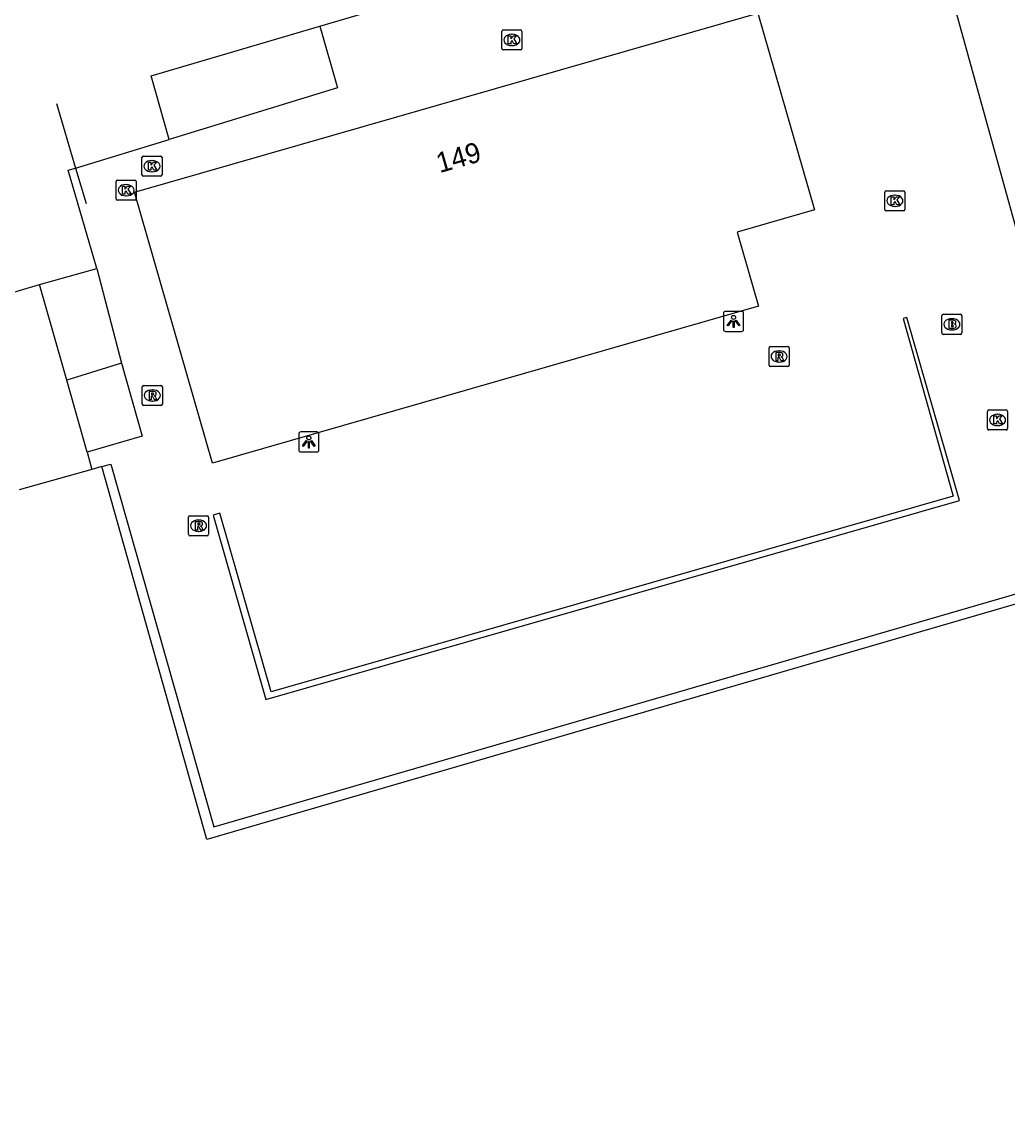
# Model space of a CAD drawing. Extents: x 162417 to 163721, y 384268 to 385416.
# Drawn here: x 162874.2 to 162923.2, y 384503.5 to 384558.2 of the extents above; entities that cross this region are included whole.
import ezdxf

# ---------------------------------------------------------------- set-up
doc = ezdxf.new("R2010")
doc.units = 0
for name, color, linetype in [('IMGEO_Brandkraan', 7, 'Continuous'), ('IMGEO_Hek', 7, 'Continuous'), ('IMGEO_Kolk', 7, 'Continuous'), ('IMGEO_Lichtpunt', 7, 'Continuous'), ('IMGEO_Muur', 7, 'Continuous'), ('IMGEO_Pand', 7, 'Continuous'), ('IMGEO_Pand_nummerreeks', 7, 'Continuous'), ('IMGEO_Rijbaan_lokaal_gesloten', 7, 'Continuous'), ('IMGEO_Rioolput', 7, 'Continuous'), ('IMGEO_Voetpad_open', 7, 'Continuous')]:
    doc.layers.add(name, color=color, linetype=linetype)

msp = doc.modelspace()

# ---------------------------------------------------------------- linework, layer by layer
at = {"layer": 'IMGEO_Brandkraan'}
for p, q in [((162919.957, 384542.765), (162919.957, 384543.617)), ((162920.032, 384543.691), (162920.884, 384543.691)), ((162920.958, 384543.617), (162920.958, 384542.765)), ((162920.445, 384543.471), (162920.47, 384543.471)), ((162920.884, 384542.691), (162920.032, 384542.691)), ((162920.468, 384542.911), (162920.443, 384542.911))]:
    msp.add_line(p, q, dxfattribs=at)
for points in [[(162919.957, 384542.765), (162919.957, 384543.617)], [(162920.032, 384543.691), (162920.884, 384543.691)], [(162920.958, 384543.617), (162920.958, 384542.765)], [(162920.305, 384543.391), (162920.305, 384542.991), (162920.518, 384542.991)], [(162920.536, 384543.391), (162920.305, 384543.391)], [(162920.484, 384543.31), (162920.43, 384543.31), (162920.43, 384543.234)], [(162920.43, 384543.234), (162920.483, 384543.234)], [(162920.492, 384543.158), (162920.43, 384543.158), (162920.43, 384543.077)], [(162920.43, 384543.077), (162920.492, 384543.077)], [(162920.884, 384542.691), (162920.032, 384542.691)]]:
    msp.add_lwpolyline(points, dxfattribs=at)
for centre, radius, start, end in [((162920.034, 384543.615), 0.0765, 91.552, 178.448), ((162920.034, 384543.615), 0.0765, 91.552, 178.448), ((162920.882, 384543.615), 0.0765, 1.552, 88.448), ((162920.882, 384543.615), 0.0765, 1.552, 88.448), ((162920.485, 384543.272), 0.0379, 267.8285, 90.9355), ((162920.493, 384543.117), 0.0404, 269.8759, 90.5077), ((162920.524, 384543.242), 0.251, 268.6676, 293.5347), ((162920.54, 384543.246), 0.145, 59.4692, 91.5367), ((162920.565, 384543.293), 0.0922, 285.5137, 58.1501), ((162920.57, 384543.101), 0.105, 301.3115, 78.989), ((162920.034, 384542.767), 0.0765, 181.552, 268.448), ((162920.034, 384542.767), 0.0765, 181.552, 268.448), ((162920.882, 384542.767), 0.0765, 271.552, 358.448), ((162920.882, 384542.767), 0.0765, 271.552, 358.448)]:
    msp.add_arc(centre, radius, start, end, dxfattribs=at)
for centre, major_axis, ratio, start_param, end_param in [((162920.444, 384543.191), (-0.387, 0.002), 0.722429, 4.712389, 7.853982), ((162920.469, 384543.191), (-0.39, 0.002), 0.717154, 1.570796, 4.712389)]:
    msp.add_ellipse(centre, major_axis=major_axis, ratio=ratio, start_param=start_param, end_param=end_param, dxfattribs=at)
at = {"layer": 'IMGEO_Hek'}
for points in [[(162875.908, 384554.172), (162876.859, 384550.963)], [(162876.859, 384550.963), (162877.381, 384549.2)]]:
    msp.add_lwpolyline(points, dxfattribs=at)
at = {"layer": 'IMGEO_Kolk'}
for p, q in [((162898.14, 384557.832), (162898.992, 384557.832)), ((162898.065, 384556.906), (162898.065, 384557.758)), ((162898.553, 384557.612), (162898.578, 384557.612)), ((162899.066, 384557.758), (162899.066, 384556.906)), ((162898.992, 384556.832), (162898.14, 384556.832)), ((162898.576, 384557.052), (162898.551, 384557.052)), ((162880.159, 384550.626), (162880.159, 384551.478)), ((162880.234, 384551.552), (162881.086, 384551.552)), ((162880.647, 384551.332), (162880.672, 384551.332)), ((162881.16, 384551.478), (162881.16, 384550.626)), ((162880.67, 384550.772), (162880.645, 384550.772)), ((162878.873, 384549.433), (162878.873, 384550.285)), ((162878.948, 384550.359), (162879.8, 384550.359)), ((162879.361, 384550.139), (162879.386, 384550.139)), ((162879.874, 384550.285), (162879.874, 384549.433)), ((162881.086, 384550.552), (162880.234, 384550.552)), ((162917.121, 384548.907), (162917.121, 384549.759)), ((162917.196, 384549.833), (162918.048, 384549.833)), ((162917.609, 384549.613), (162917.634, 384549.613)), ((162918.122, 384549.759), (162918.122, 384548.907)), ((162879.8, 384549.359), (162878.948, 384549.359)), ((162879.384, 384549.579), (162879.359, 384549.579)), ((162917.632, 384549.053), (162917.607, 384549.053)), ((162918.048, 384548.833), (162917.196, 384548.833)), ((162922.227, 384538.009), (162922.227, 384538.861)), ((162922.302, 384538.935), (162923.154, 384538.935)), ((162922.715, 384538.715), (162922.74, 384538.715)), ((162923.228, 384538.861), (162923.228, 384538.009)), ((162922.738, 384538.155), (162922.713, 384538.155)), ((162923.154, 384537.935), (162922.302, 384537.935))]:
    msp.add_line(p, q, dxfattribs=at)
for points in [[(162898.14, 384557.832), (162898.992, 384557.832)], [(162898.065, 384556.906), (162898.065, 384557.758)], [(162898.386, 384557.532), (162898.509, 384557.532), (162898.509, 384557.381), (162898.639, 384557.532), (162898.803, 384557.532), (162898.657, 384557.381), (162898.81, 384557.132), (162898.658, 384557.132), (162898.573, 384557.296), (162898.509, 384557.229), (162898.509, 384557.132), (162898.386, 384557.132), (162898.386, 384557.532)], [(162899.066, 384557.758), (162899.066, 384556.906)], [(162898.992, 384556.832), (162898.14, 384556.832)], [(162880.159, 384550.626), (162880.159, 384551.478)], [(162880.234, 384551.552), (162881.086, 384551.552)], [(162880.48, 384551.252), (162880.603, 384551.252), (162880.603, 384551.101), (162880.733, 384551.252), (162880.897, 384551.252), (162880.751, 384551.101), (162880.904, 384550.852), (162880.752, 384550.852), (162880.667, 384551.016), (162880.603, 384550.949), (162880.603, 384550.852), (162880.48, 384550.852), (162880.48, 384551.252)], [(162881.16, 384551.478), (162881.16, 384550.626)], [(162878.873, 384549.433), (162878.873, 384550.285)], [(162878.948, 384550.359), (162879.8, 384550.359)], [(162879.874, 384550.285), (162879.874, 384549.433)], [(162881.086, 384550.552), (162880.234, 384550.552)], [(162879.194, 384550.059), (162879.317, 384550.059), (162879.317, 384549.908), (162879.447, 384550.059), (162879.611, 384550.059), (162879.465, 384549.908), (162879.618, 384549.659), (162879.466, 384549.659), (162879.381, 384549.823), (162879.317, 384549.756), (162879.317, 384549.659), (162879.194, 384549.659), (162879.194, 384550.059)], [(162917.121, 384548.907), (162917.121, 384549.759)], [(162917.196, 384549.833), (162918.048, 384549.833)], [(162918.122, 384549.759), (162918.122, 384548.907)], [(162879.8, 384549.359), (162878.948, 384549.359)], [(162917.442, 384549.533), (162917.565, 384549.533), (162917.565, 384549.382), (162917.695, 384549.533), (162917.859, 384549.533), (162917.713, 384549.382), (162917.866, 384549.133), (162917.714, 384549.133), (162917.629, 384549.297), (162917.565, 384549.23), (162917.565, 384549.133), (162917.442, 384549.133), (162917.442, 384549.533)], [(162918.048, 384548.833), (162917.196, 384548.833)], [(162922.227, 384538.009), (162922.227, 384538.861)], [(162922.302, 384538.935), (162923.154, 384538.935)], [(162922.548, 384538.635), (162922.671, 384538.635), (162922.671, 384538.484), (162922.801, 384538.635), (162922.965, 384538.635), (162922.819, 384538.484), (162922.972, 384538.235), (162922.82, 384538.235), (162922.735, 384538.399), (162922.671, 384538.332), (162922.671, 384538.235), (162922.548, 384538.235), (162922.548, 384538.635)], [(162923.228, 384538.861), (162923.228, 384538.009)], [(162923.154, 384537.935), (162922.302, 384537.935)]]:
    msp.add_lwpolyline(points, dxfattribs=at)
for centre, start, end in [((162898.142, 384557.756), 91.552, 178.448), ((162898.142, 384557.756), 91.552, 178.448), ((162898.99, 384557.756), 1.552, 88.448), ((162898.99, 384557.756), 1.552, 88.448), ((162898.142, 384556.908), 181.552, 268.448), ((162898.142, 384556.908), 181.552, 268.448), ((162898.99, 384556.908), 271.552, 358.448), ((162898.99, 384556.908), 271.552, 358.448), ((162880.236, 384551.476), 91.552, 178.448), ((162880.236, 384551.476), 91.552, 178.448), ((162881.084, 384551.476), 1.552, 88.448), ((162881.084, 384551.476), 1.552, 88.448), ((162878.95, 384550.283), 91.552, 178.448), ((162878.95, 384550.283), 91.552, 178.448), ((162879.798, 384550.283), 1.552, 88.448), ((162879.798, 384550.283), 1.552, 88.448), ((162880.236, 384550.628), 181.552, 268.448), ((162880.236, 384550.628), 181.552, 268.448), ((162881.084, 384550.628), 271.552, 358.448), ((162881.084, 384550.628), 271.552, 358.448), ((162917.198, 384549.757), 91.552, 178.448), ((162917.198, 384549.757), 91.552, 178.448), ((162918.046, 384549.757), 1.552, 88.448), ((162918.046, 384549.757), 1.552, 88.448), ((162878.95, 384549.435), 181.552, 268.448), ((162878.95, 384549.435), 181.552, 268.448), ((162879.798, 384549.435), 271.552, 358.448), ((162879.798, 384549.435), 271.552, 358.448), ((162917.198, 384548.909), 181.552, 268.448), ((162917.198, 384548.909), 181.552, 268.448), ((162918.046, 384548.909), 271.552, 358.448), ((162918.046, 384548.909), 271.552, 358.448), ((162922.304, 384538.859), 91.552, 178.448), ((162922.304, 384538.859), 91.552, 178.448), ((162923.152, 384538.859), 1.552, 88.448), ((162923.152, 384538.859), 1.552, 88.448), ((162922.304, 384538.011), 181.552, 268.448), ((162922.304, 384538.011), 181.552, 268.448), ((162923.152, 384538.011), 271.552, 358.448), ((162923.152, 384538.011), 271.552, 358.448)]:
    msp.add_arc(centre, 0.0765, start, end, dxfattribs=at)
for centre, major_axis, ratio, start_param, end_param in [((162898.552, 384557.332), (-0.387, 0.002), 0.722429, 4.712389, 7.853982), ((162898.577, 384557.332), (-0.39, 0.002), 0.717154, 1.570796, 4.712389), ((162880.646, 384551.052), (-0.387, 0.002), 0.722429, 4.712389, 7.853982), ((162880.671, 384551.052), (-0.39, 0.002), 0.717154, 1.570796, 4.712389), ((162879.36, 384549.859), (-0.387, 0.002), 0.722429, 4.712389, 7.853982), ((162879.385, 384549.859), (-0.39, 0.002), 0.717154, 1.570796, 4.712389), ((162917.608, 384549.333), (-0.387, 0.002), 0.722429, 4.712389, 7.853982), ((162917.633, 384549.333), (-0.39, 0.002), 0.717154, 1.570796, 4.712389), ((162922.714, 384538.435), (-0.387, 0.002), 0.722429, 4.712389, 7.853982), ((162922.739, 384538.435), (-0.39, 0.002), 0.717154, 1.570796, 4.712389)]:
    msp.add_ellipse(centre, major_axis=major_axis, ratio=ratio, start_param=start_param, end_param=end_param, dxfattribs=at)
at = {"layer": 'IMGEO_Lichtpunt'}
for p, q in [((162909.095, 384543.737), (162909.095, 384542.93)), ((162909.095, 384543.737), (162909.095, 384542.93)), ((162909.997, 384543.832), (162909.189, 384543.832)), ((162909.997, 384543.832), (162909.189, 384543.832)), ((162910.091, 384542.93), (162910.091, 384543.737)), ((162910.091, 384542.93), (162910.091, 384543.737)), ((162909.189, 384542.836), (162909.997, 384542.836)), ((162909.189, 384542.836), (162909.997, 384542.836)), ((162887.964, 384537.744), (162887.964, 384536.937)), ((162887.964, 384537.744), (162887.964, 384536.937)), ((162888.866, 384537.839), (162888.058, 384537.839)), ((162888.866, 384537.839), (162888.058, 384537.839)), ((162888.96, 384536.937), (162888.96, 384537.744)), ((162888.96, 384536.937), (162888.96, 384537.744)), ((162888.058, 384536.843), (162888.866, 384536.843)), ((162888.058, 384536.843), (162888.866, 384536.843))]:
    msp.add_line(p, q, dxfattribs=at)
for points in [[(162909.469, 384543.401), (162909.508, 384543.373), (162909.32, 384543.111), (162909.282, 384543.138), (162909.469, 384543.401)], [(162909.571, 384543.353), (162909.618, 384543.353), (162909.618, 384543.031), (162909.571, 384543.031), (162909.571, 384543.353)], [(162909.681, 384543.373), (162909.719, 384543.4), (162909.906, 384543.138), (162909.867, 384543.11), (162909.681, 384543.373)], [(162888.338, 384537.408), (162888.377, 384537.38), (162888.189, 384537.118), (162888.151, 384537.145), (162888.338, 384537.408)], [(162888.44, 384537.36), (162888.487, 384537.36), (162888.487, 384537.038), (162888.44, 384537.038), (162888.44, 384537.36)], [(162888.55, 384537.38), (162888.588, 384537.407), (162888.775, 384537.145), (162888.736, 384537.117), (162888.55, 384537.38)]]:
    msp.add_lwpolyline(points, dxfattribs=at)
for centre in [(162909.594, 384543.535), (162888.463, 384537.542)]:
    msp.add_circle(centre, 0.0994, dxfattribs=at)
for centre, start, end in [((162909.189, 384543.737), 90, 180), ((162909.189, 384543.737), 90, 180), ((162909.997, 384543.737), 0, 90), ((162909.997, 384543.737), 0, 90), ((162909.189, 384542.93), 180, 270), ((162909.189, 384542.93), 180, 270), ((162909.997, 384542.93), 270, 0), ((162909.997, 384542.93), 270, 360), ((162888.058, 384537.744), 90, 180), ((162888.058, 384537.744), 90, 180), ((162888.866, 384537.744), 0, 90), ((162888.866, 384537.744), 0, 90), ((162888.058, 384536.937), 180, 270), ((162888.058, 384536.937), 180, 270), ((162888.866, 384536.937), 270, 0), ((162888.866, 384536.937), 270, 360)]:
    msp.add_arc(centre, 0.0946, start, end, dxfattribs=at)
at = {"layer": 'IMGEO_Muur'}
for points in [[(162918.22, 384543.528), (162918.03, 384543.473), (162920.528, 384534.642), (162892.486, 384526.608), (162886.585, 384524.917), (162884.04, 384533.796), (162883.705, 384533.701), (162886.331, 384524.539), (162920.833, 384534.428), (162918.22, 384543.528)], [(162878.17, 384536.114), (162878.614, 384536.239), (162883.731, 384518.208), (162927.298, 384530.854), (162927.217, 384531.137), (162927.658, 384531.274)], [(162968.826, 384503.475), (162935.509, 384505.709), (162935.475, 384505.306), (162933.994, 384505.388), (162934.026, 384506.507), (162934.243, 384506.512), (162927.431, 384530.386), (162883.395, 384517.577), (162878.17, 384536.114)]]:
    msp.add_lwpolyline(points, dxfattribs=at)
at = {"layer": 'IMGEO_Pand'}
msp.add_lwpolyline([(162910.835, 384544.088), (162883.663, 384536.285), (162879.794, 384549.759), (162910.81, 384558.667), (162913.62, 384548.884), (162909.775, 384547.78), (162910.835, 384544.088)], dxfattribs=at)
at = {"layer": 'IMGEO_Rijbaan_lokaal_gesloten'}
msp.add_lwpolyline([(162930.167, 384545.925), (162924.649, 384544.377), (162919.95, 384561.313)], dxfattribs=at)
at = {"layer": 'IMGEO_Rioolput'}
for p, q in [((162911.358, 384541.165), (162911.358, 384542.017)), ((162911.433, 384542.091), (162912.285, 384542.091)), ((162912.359, 384542.017), (162912.359, 384541.165)), ((162911.846, 384541.871), (162911.871, 384541.871)), ((162912.285, 384541.091), (162911.433, 384541.091)), ((162911.869, 384541.311), (162911.844, 384541.311)), ((162880.175, 384539.226), (162880.175, 384540.078)), ((162880.25, 384540.152), (162881.102, 384540.152)), ((162880.663, 384539.932), (162880.688, 384539.932)), ((162881.176, 384540.078), (162881.176, 384539.226)), ((162880.686, 384539.372), (162880.661, 384539.372)), ((162881.102, 384539.152), (162880.25, 384539.152)), ((162882.478, 384532.748), (162882.478, 384533.6)), ((162882.553, 384533.674), (162883.405, 384533.674)), ((162882.966, 384533.454), (162882.991, 384533.454)), ((162883.479, 384533.6), (162883.479, 384532.748)), ((162883.405, 384532.674), (162882.553, 384532.674)), ((162882.989, 384532.894), (162882.964, 384532.894))]:
    msp.add_line(p, q, dxfattribs=at)
for points in [[(162911.358, 384541.165), (162911.358, 384542.017)], [(162911.433, 384542.091), (162912.285, 384542.091)], [(162912.359, 384542.017), (162912.359, 384541.165)], [(162911.947, 384541.789), (162911.695, 384541.791), (162911.695, 384541.391)], [(162911.695, 384541.391), (162911.819, 384541.391), (162911.819, 384541.553), (162911.83, 384541.553)], [(162911.873, 384541.71), (162911.819, 384541.71), (162911.819, 384541.629)], [(162911.819, 384541.629), (162911.871, 384541.629)], [(162911.877, 384541.524), (162911.948, 384541.391), (162912.088, 384541.391), (162912.023, 384541.517)], [(162912.285, 384541.091), (162911.433, 384541.091)], [(162880.175, 384539.226), (162880.175, 384540.078)], [(162880.25, 384540.152), (162881.102, 384540.152)], [(162880.764, 384539.85), (162880.512, 384539.852), (162880.512, 384539.452)], [(162880.69, 384539.771), (162880.636, 384539.771), (162880.636, 384539.69)], [(162881.176, 384540.078), (162881.176, 384539.226)], [(162880.512, 384539.452), (162880.636, 384539.452), (162880.636, 384539.614), (162880.647, 384539.614)], [(162880.636, 384539.69), (162880.688, 384539.69)], [(162880.694, 384539.585), (162880.765, 384539.452), (162880.905, 384539.452), (162880.84, 384539.578)], [(162881.102, 384539.152), (162880.25, 384539.152)], [(162882.478, 384532.748), (162882.478, 384533.6)], [(162882.553, 384533.674), (162883.405, 384533.674)], [(162883.067, 384533.372), (162882.815, 384533.374), (162882.815, 384532.974)], [(162882.993, 384533.293), (162882.939, 384533.293), (162882.939, 384533.212)], [(162882.939, 384533.212), (162882.991, 384533.212)], [(162883.479, 384533.6), (162883.479, 384532.748)], [(162883.405, 384532.674), (162882.553, 384532.674)], [(162882.815, 384532.974), (162882.939, 384532.974), (162882.939, 384533.136), (162882.95, 384533.136)], [(162882.997, 384533.107), (162883.068, 384532.974), (162883.208, 384532.974), (162883.143, 384533.1)]]:
    msp.add_lwpolyline(points, dxfattribs=at)
for centre, radius, start, end in [((162911.435, 384542.015), 0.0765, 91.552, 178.448), ((162911.435, 384542.015), 0.0765, 91.552, 178.448), ((162912.283, 384542.015), 0.0765, 1.552, 88.448), ((162912.283, 384542.015), 0.0765, 1.552, 88.448), ((162911.829, 384541.5), 0.0533, 26.0293, 88.6989), ((162911.855, 384541.818), 0.19, 274.7715, 282.9687), ((162911.879, 384541.614), 0.0964, 77.0061, 93.1865), ((162911.893, 384541.671), 0.0378, 276.6634, 79.6772), ((162911.946, 384541.679), 0.109, 350.3612, 89.416), ((162911.944, 384541.679), 0.112, 277.5842, 350.9817), ((162911.928, 384541.464), 0.108, 29.5134, 73.7905), ((162911.435, 384541.167), 0.0765, 181.552, 268.448), ((162911.435, 384541.167), 0.0765, 181.552, 268.448), ((162912.283, 384541.167), 0.0765, 271.552, 358.448), ((162912.283, 384541.167), 0.0765, 271.552, 358.448), ((162880.252, 384540.076), 0.0765, 91.552, 178.448), ((162880.252, 384540.076), 0.0765, 91.552, 178.448), ((162880.696, 384539.675), 0.0964, 77.0061, 93.1865), ((162880.71, 384539.732), 0.0378, 276.6634, 79.6772), ((162880.763, 384539.74), 0.109, 350.3612, 89.416), ((162881.1, 384540.076), 0.0765, 1.552, 88.448), ((162881.1, 384540.076), 0.0765, 1.552, 88.448), ((162880.252, 384539.228), 0.0765, 181.552, 268.448), ((162880.252, 384539.228), 0.0765, 181.552, 268.448), ((162880.646, 384539.561), 0.0533, 26.0293, 88.6989), ((162880.672, 384539.879), 0.19, 274.7715, 282.9687), ((162880.761, 384539.74), 0.112, 277.5842, 350.9817), ((162880.745, 384539.525), 0.108, 29.5134, 73.7905), ((162881.1, 384539.228), 0.0765, 271.552, 358.448), ((162881.1, 384539.228), 0.0765, 271.552, 358.448), ((162882.555, 384533.598), 0.0765, 91.552, 178.448), ((162882.555, 384533.598), 0.0765, 91.552, 178.448), ((162882.975, 384533.401), 0.19, 274.7715, 282.9687), ((162882.999, 384533.197), 0.0964, 77.0061, 93.1865), ((162883.013, 384533.254), 0.0378, 276.6634, 79.6772), ((162883.066, 384533.262), 0.109, 350.3612, 89.416), ((162883.064, 384533.262), 0.112, 277.5842, 350.9817), ((162883.403, 384533.598), 0.0765, 1.552, 88.448), ((162883.403, 384533.598), 0.0765, 1.552, 88.448), ((162882.555, 384532.75), 0.0765, 181.552, 268.448), ((162882.555, 384532.75), 0.0765, 181.552, 268.448), ((162882.949, 384533.083), 0.0533, 26.0293, 88.6989), ((162883.048, 384533.047), 0.108, 29.5134, 73.7905), ((162883.403, 384532.75), 0.0765, 271.552, 358.448), ((162883.403, 384532.75), 0.0765, 271.552, 358.448)]:
    msp.add_arc(centre, radius, start, end, dxfattribs=at)
for centre, major_axis, ratio, start_param, end_param in [((162911.845, 384541.591), (-0.387, 0.002), 0.722429, 4.712389, 7.853982), ((162911.87, 384541.591), (-0.39, 0.002), 0.717154, 1.570796, 4.712389), ((162880.662, 384539.652), (-0.387, 0.002), 0.722429, 4.712389, 7.853982), ((162880.687, 384539.652), (-0.39, 0.002), 0.717154, 1.570796, 4.712389), ((162882.965, 384533.174), (-0.387, 0.002), 0.722429, 4.712389, 7.853982), ((162882.99, 384533.174), (-0.39, 0.002), 0.717154, 1.570796, 4.712389)]:
    msp.add_ellipse(centre, major_axis=major_axis, ratio=ratio, start_param=start_param, end_param=end_param, dxfattribs=at)
at = {"layer": 'IMGEO_Voetpad_open'}
for points in [[(162889.014, 384558.009), (162918.058, 384566.545), (162918.465, 384566.665)], [(162881.515, 384552.386), (162880.611, 384555.539), (162889.014, 384558.009)], [(162889.014, 384558.009), (162889.895, 384554.947), (162881.515, 384552.386)], [(162877.914, 384545.97), (162876.495, 384550.852), (162876.859, 384550.963), (162881.515, 384552.386)], [(162875.066, 384545.17), (162877.914, 384545.97)], [(162877.914, 384545.97), (162879.14, 384541.259)], [(162871.431, 384544.085), (162875.066, 384545.17)], [(162876.416, 384540.405), (162875.066, 384545.17)], [(162879.14, 384541.259), (162876.416, 384540.405)], [(162879.14, 384541.259), (162880.168, 384537.622), (162877.429, 384536.831)], [(162877.429, 384536.831), (162876.416, 384540.405)], [(162877.429, 384536.831), (162877.674, 384535.975)], [(162877.674, 384535.975), (162874.052, 384534.956)], [(162878.17, 384536.114), (162877.674, 384535.975)]]:
    msp.add_lwpolyline(points, dxfattribs=at)

# ---------------------------------------------------------------- texts
at = {"layer": 'IMGEO_Pand_nummerreeks'}
msp.add_text('149', height=1, rotation=16.0244, dxfattribs=at).set_placement((162894.971, 384550.705))

doc.saveas('drawing.dxf')
